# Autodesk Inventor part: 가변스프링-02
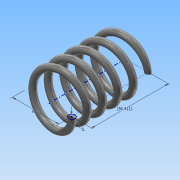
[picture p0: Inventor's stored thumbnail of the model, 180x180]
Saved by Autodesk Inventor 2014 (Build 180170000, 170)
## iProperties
Created: 2015-09
Part Number: 가변스프링-02
Material: 강철, 탄소
Document SubType Name: Modeling
Designer: study
Density: 7.87 g/cm^3
Appearance: 반연마
Mass: 18.7976 g
Surface Area: 32.4648 cm^2
Volume: 2.38851 cm^3
Author: study
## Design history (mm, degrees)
sketch "스케치1"
  geometry: L1 (0, 0)-(11, 0); L2 (11, 0)-(11, 29.043); L3 (11, 29.043)-(0, 29.043); L4 (0, 29.043)-(0, 0); C1 r 1.5 at (11, 0)
  constraints: 8 end point, 2 parallel, 1 centre point, 1 coincident, 1 horizontal, 1 perpendicular
  dimensions: "d0" = 29.04259 distance of L1.end L2.end (derived); "d1" = 22 diameter of L2 L4; "d2" = 3 diameter of C1
feature "코일1" sketch "스케치1" pitch "d3" = 10; turns "d5" = 5; dims "d4" = 29.04259 (= d0), "d6" = 0, angle "d7" = 90 deg, angle "d8" = 90 deg, "d9" = 0, "d10" = 0
node "작업 평면1"
sketch "스케치2"
  geometry: L1 (-12.5, 0)-(-9.5, 0) reference; 1 further point
  constraints: 1 horizontal alignment
extrude "돌출1" cut sketch "스케치2" stored distance "d12" = 10; taper "d13" = 0 deg
node "작업 평면2"
sketch "스케치3"
  geometry: L1 (-9.5, 0)-(-12.5, 0) reference; 1 further point
  constraints: 1 horizontal alignment
extrude "돌출2" cut sketch "스케치3" distance "d15" = 10; taper "d16" = 0 deg
node "솔리드1"
node "절단 모서리 투영1"
node "절단 모서리 투영2"
other parameters: "d11" = 0, "d14" = 29.04259 (= d0)
